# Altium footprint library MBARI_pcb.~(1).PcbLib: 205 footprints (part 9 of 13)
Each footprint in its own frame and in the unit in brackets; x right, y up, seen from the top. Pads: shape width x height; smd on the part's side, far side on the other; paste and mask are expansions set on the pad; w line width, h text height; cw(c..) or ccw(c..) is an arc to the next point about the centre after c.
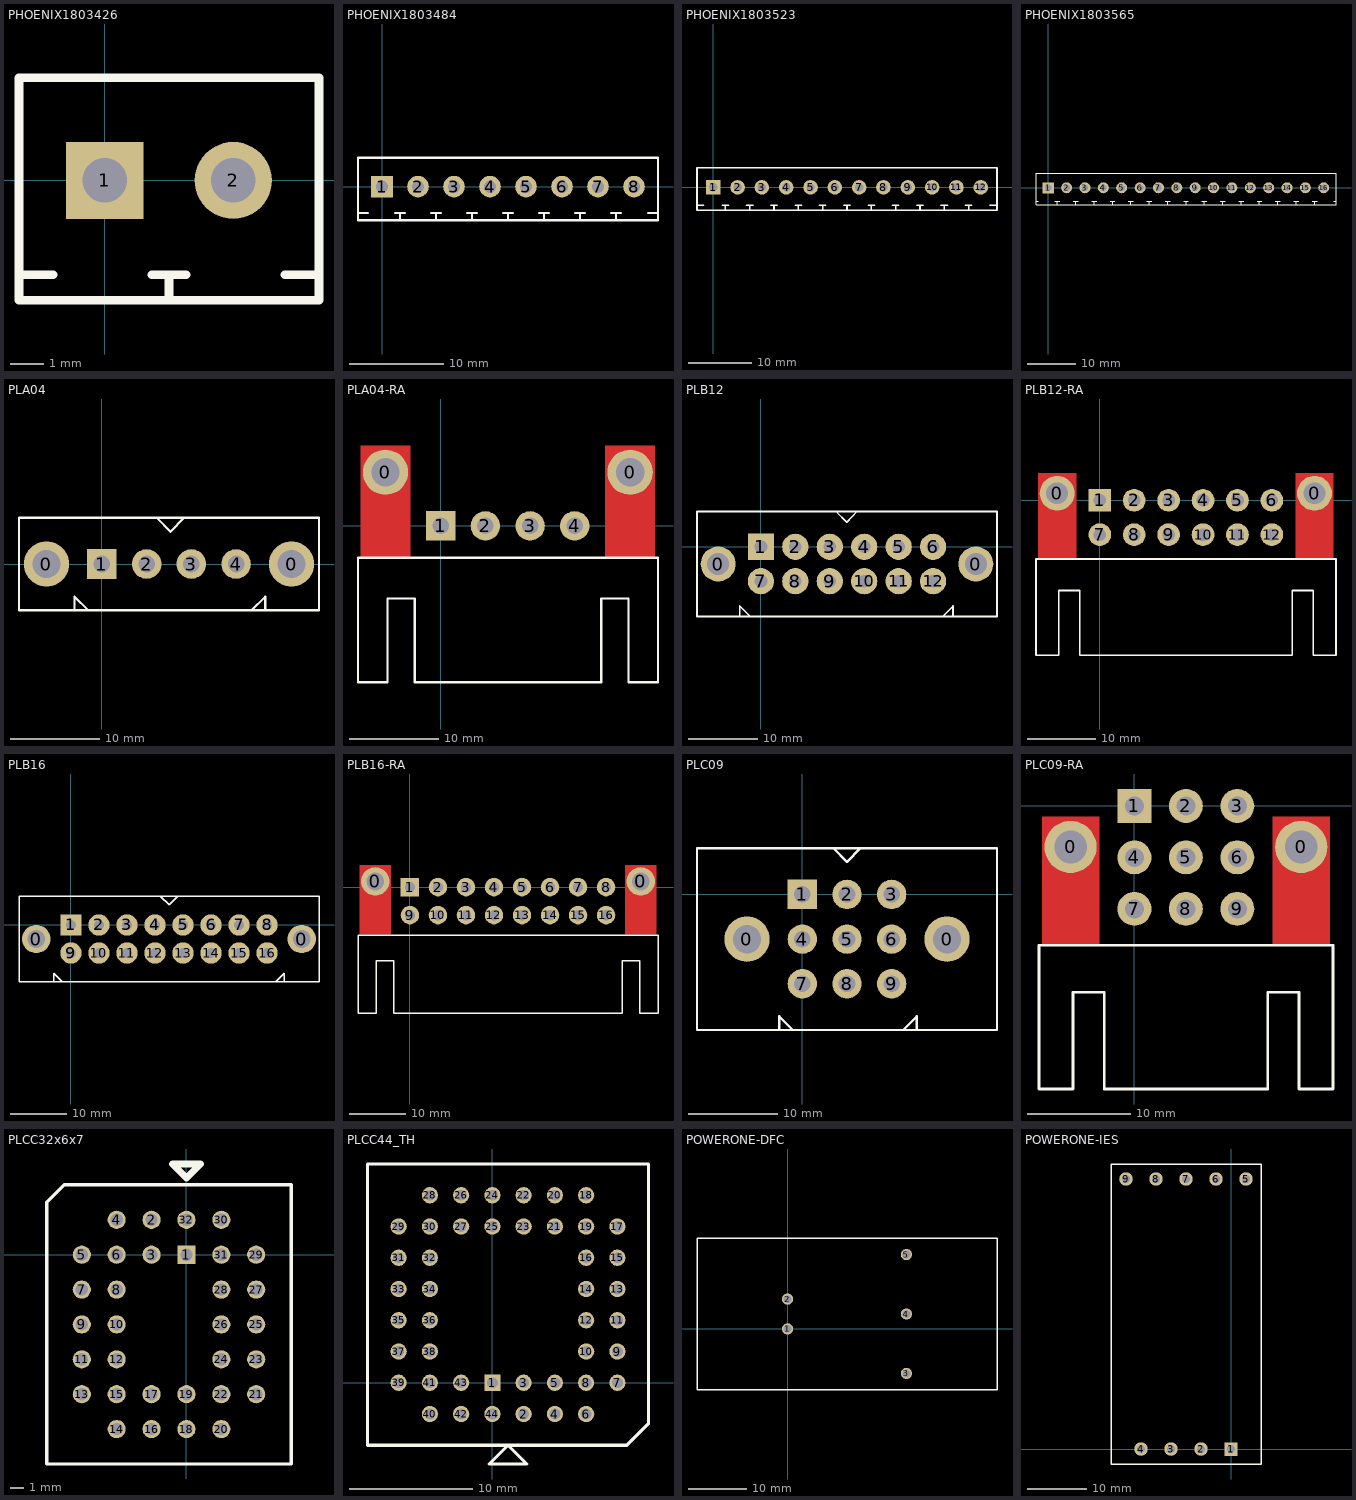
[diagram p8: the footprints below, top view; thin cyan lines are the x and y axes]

## PHOENIX1803426 [mil]
pads (2):
  rect 90x90 hole 52: 1(0,0)
  round 90 hole 52: 2(150,0)
TopOverlay:
  lines w10: -100,-110 -60,-110 ; 55,-110 95,-110 ; 75,-140 75,-110 ; 210,-110 250,-110 ; -100,-140 250,-140 250,120 -100,120 -100,-140

## PHOENIX1803484 [mil]
pads (8):
  rect 90x90 hole 52: 1(0,0)
  round 90 hole 52: 2(150,0) 3(300,0) 4(450,0) 5(600,0) 6(750,0) 7(900,0) 8(1050,0)
TopOverlay:
  lines w10: -100,-110 -60,-110 ; 55,-110 95,-110 ; 75,-140 75,-110 ; 205,-110 245,-110 ; 225,-140 225,-110 ; 355,-110 395,-110 ; 375,-140 375,-110 ; 505,-110 545,-110 ; 525,-140 525,-110 ; 655,-110 695,-110 ; 675,-140 675,-110 ; 805,-110 845,-110 ; 825,-140 825,-110 ; 955,-110 995,-110 ; 975,-140 975,-110 ; 1110,-110 1150,-110 ; -100,-140 -100,120 1150,120 1150,-140 -100,-140

## PHOENIX1803523 [mil]
pads (12):
  rect 90x90 hole 52: 1(0,0)
  round 90 hole 52: 2(150,0) 3(300,0) 4(450,0) 5(600,0) 6(750,0) 7(900,0) 8(1050,0) 9(1200,0) 10(1350,0) 11(1500,0) 12(1650,0)
TopOverlay:
  lines w10: -100,-110 -60,-110 ; 55,-110 95,-110 ; 75,-140 75,-110 ; 205,-110 245,-110 ; 225,-140 225,-110 ; 355,-110 395,-110 ; 375,-140 375,-110 ; 505,-110 545,-110 ; 525,-140 525,-110 ; 655,-110 695,-110 ; 675,-140 675,-110 ; 805,-110 845,-110 ; 825,-140 825,-110 ; 955,-110 995,-110 ; 975,-140 975,-110 ; 1105,-110 1145,-110 ; 1125,-140 1125,-110 ; 1255,-110 1295,-110 ; 1275,-140 1275,-110 ; 1405,-110 1445,-110 ; 1425,-140 1425,-110 ; 1555,-110 1595,-110 ; 1575,-140 1575,-110 ; 1705,-110 1745,-110 ; -100,-140 -100,120 1750,120 1750,-140 -100,-140

## PHOENIX1803565 [mil]
pads (16):
  rect 90x90 hole 52: 1(0,0)
  round 90 hole 52: 2(150,0) 3(300,0) 4(450,0) 5(600,0) 6(750,0) 7(900,0) 8(1050,0) 9(1200,0) 10(1350,0) 11(1500,0) 12(1650,0) 13(1800,0) 14(1950,0) 15(2100,0) 16(2250,0)
TopOverlay:
  lines w10: -100,-110 -80,-110 ; 55,-110 95,-110 ; 75,-140 75,-110 ; 205,-110 245,-110 ; 225,-140 225,-110 ; 355,-110 395,-110 ; 375,-140 375,-110 ; 505,-110 545,-110 ; 525,-140 525,-110 ; 655,-110 695,-110 ; 675,-140 675,-110 ; 805,-110 845,-110 ; 825,-140 825,-110 ; 955,-110 995,-110 ; 975,-140 975,-110 ; 1105,-110 1145,-110 ; 1125,-140 1125,-110 ; 1255,-110 1295,-110 ; 1275,-140 1275,-110 ; 1405,-110 1445,-110 ; 1425,-140 1425,-110 ; 1555,-110 1595,-110 ; 1575,-140 1575,-110 ; 1705,-110 1745,-110 ; 1725,-140 1725,-110 ; 1855,-110 1895,-110 ; 1875,-140 1875,-110 ; 2005,-110 2045,-110 ; 2025,-140 2025,-110 ; 2155,-110 2195,-110 ; 2175,-140 2175,-110 ; 2330,-110 2350,-110 ; -100,-140 2350,-140 2350,120 -100,120 -100,-140

## PLA04 [mil] "Positronic 1x4 pin"
pads (6):
  round 200 hole 125: 0(-244.5,0) 0(835.5,0)
  rect 130x130 hole 73: 1(0,0)
  round 130 hole 73: 2(197,0) 3(394,0) 4(591,0)
TopOverlay:
  lines w10: -120.5,-204 -120.5,-144 -60.5,-204 ; 242,204 302.5,142.5 362,204 ; 659.5,-204 719.5,-144 719.5,-204 ; -365.5,-204 -365.5,204 956.5,204 956.5,-204 -365.5,-204

## PLA04-RA [mil]
pads (6):
  round 200 hole 125: 0(-244.5,237) 0(835.5,237)
  rect 130x130 hole 73: 1(0,0)
  round 130 hole 73: 2(197,0) 3(394,0) 4(591,0)
TopLayer:
  rectangle: 725.5,-138 945.5,354
  rectangle: -354.5,-138 -134.5,354
TopOverlay:
  lines w10: -365.5,-690 -235.5,-690 -235.5,-320 -115.5,-320 -115.5,-690 708.5,-690 708.5,-320 828.5,-320 828.5,-690 958.5,-690 958.5,-140 -365.5,-140 -365.5,-690

## PLB12 [mil] "Positronic 2x6 pin"
pads (14):
  round 200 hole 125: 0(-244.5,-98.5) 0(1229.5,-98.5)
  rect 150x150 hole 73: 1(0,0)
  round 150 hole 73: 2(197,0) 3(394,0) 4(591,0) 5(788,0) 6(985,0) 7(0,-197) 8(197,-197) 9(394,-197) 10(591,-197) 11(788,-197) 12(985,-197)
TopOverlay:
  lines w10: -120.5,-398.5 -120.5,-338.5 -60.5,-398.5 ; 429.5,201.5 490,140 549.5,201.5 ; 1039.5,-398.5 1099.5,-338.5 1099.5,-398.5 ; -365.5,-398.5 1350.5,-398.5 1350.5,201.5 -365.5,201.5 -365.5,-398.5

## PLB12-RA [mil]
pads (14):
  round 200 hole 125: 0(-244.5,40) 0(1229.5,40)
  rect 130x130 hole 73: 1(0,0)
  round 130 hole 73: 2(197,0) 3(394,0) 4(591,0) 5(788,0) 6(985,0) 7(0,-197) 8(197,-197) 9(394,-197) 10(591,-197) 11(788,-197) 12(985,-197)
TopLayer:
  rectangle: -354.5,-335 -134.5,157
  rectangle: 1119.5,-335 1339.5,157
TopOverlay:
  lines w10: -365.5,-887 -365.5,-337 1352.5,-337 1352.5,-887 1222.5,-887 1222.5,-517 1102.5,-517 1102.5,-887 -115.5,-887 -115.5,-517 -235.5,-517 -235.5,-887 -365.5,-887

## PLB16 [mil] "Positronic 2x8 pins"
pads (18):
  round 200 hole 125: 0(-244.5,-98.5) 0(1623.5,-98.5)
  rect 150x150 hole 73: 1(0,0)
  round 150 hole 73: 2(197,0) 3(394,0) 4(591,0) 5(788,0) 6(985,0) 7(1182,0) 8(1379,0) 9(0,-197) 10(197,-197) 11(394,-197) 12(591,-197) 13(788,-197) 14(985,-197) 15(1182,-197) 16(1379,-197)
TopOverlay:
  lines w10: -120.5,-398.5 -120.5,-338.5 -60.5,-398.5 ; 629.5,201.5 689.5,141.5 749.5,201.5 ; 1439.5,-398.5 1499.5,-338.5 1499.5,-398.5 ; -365.5,-398.5 -365.5,201.5 1744.5,201.5 1744.5,-398.5 -365.5,-398.5

## PLB16-RA [mil]
pads (18):
  round 200 hole 125: 0(-244.5,40) 0(1623.5,40)
  rect 130x130 hole 73: 1(0,0)
  round 130 hole 73: 2(197,0) 3(394,0) 4(591,0) 5(788,0) 6(985,0) 7(1182,0) 8(1379,0) 9(0,-197) 10(197,-197) 11(394,-197) 12(591,-197) 13(788,-197) 14(985,-197) 15(1182,-197) 16(1379,-197)
TopLayer:
  rectangle: -354.5,-335 -134.5,157
  rectangle: 1513.5,-335 1733.5,157
TopOverlay:
  lines w10: -365.5,-887 -365.5,-337 1744.5,-337 1744.5,-887 1614.5,-887 1614.5,-517 1494.5,-517 1494.5,-887 -115.5,-887 -115.5,-517 -235.5,-517 -235.5,-887 -365.5,-887

## PLC09 [mil] "Positronic 3x3 pins"
pads (11):
  round 200 hole 125: 0(-244.5,-197) 0(638.5,-197)
  rect 130x130 hole 73: 1(0,0)
  round 130 hole 73: 2(197,0) 3(394,0) 4(0,-197) 5(197,-197) 6(394,-197) 7(0,-394) 8(197,-394) 9(394,-394)
TopOverlay:
  lines w10: -102,-598 -102,-538 -42,-598 ; 136.5,205 197,143.5 256.5,205 ; 445,-598 505,-538 505,-598 ; -465,-598 -465,204 859,204 859,-598 -465,-598

## PLC09-RA [mil]
pads (11):
  round 200 hole 125: 0(-244.5,-157) 0(638.5,-157)
  rect 130x130 hole 73: 1(0,0)
  round 130 hole 73: 2(197,0) 3(394,0) 4(0,-197) 5(197,-197) 6(394,-197) 7(0,-394) 8(197,-394) 9(394,-394)
TopLayer:
  rectangle: 528.5,-532 748.5,-40
  rectangle: -354.5,-532 -134.5,-40
TopOverlay:
  lines w10: -365.5,-1084 -235.5,-1084 -235.5,-714 -115.5,-714 -115.5,-1084 510.5,-1084 510.5,-714 630.5,-714 630.5,-1084 760.5,-1084 760.5,-534 -365.5,-534 -365.5,-1084

## PLCC32x6x7 [mil]
pads (32):
  rect 52x52 hole 35: 1(0,0)
  round 52 hole 35: 2(-100,100) 3(-100,0) 4(-200,100) 5(-300,0) 6(-200,0) 7(-300,-100) 8(-200,-100) 9(-300,-200) 10(-200,-200) 11(-300,-300) 12(-200,-300) 13(-300,-400) 14(-200,-500) 15(-200,-400) 16(-100,-500) 17(-100,-400) 18(0,-500) 19(0,-400) 20(100,-500) 21(200,-400) 22(100,-400) 23(200,-300) 24(100,-300) 25(200,-200) 26(100,-200) 27(200,-100) 28(100,-100) 29(200,0) 30(100,100) 31(100,0) 32(0,100)
TopOverlay:
  lines w10: -400,-600 300,-600 300,200 -350,200 -400,150 -400,-600
  lines w20: -40,260 0,220 40,260 -40,260

## PLCC44_TH [mil]
pads (44):
  rect 52x52 hole 35: 1(0,0)
  round 52 hole 35: 2(100,-100) 3(100,0) 4(200,-100) 5(200,0) 6(300,-100) 7(400,0) 8(300,0) 9(400,100) 10(300,100) 11(400,200) 12(300,200) 13(400,300) 14(300,300) 15(400,400) 16(300,400) 17(400,500) 18(300,600) 19(300,500) 20(200,600) 21(200,500) 22(100,600) 23(100,500) 24(0,600) 25(0,500) 26(-100,600) 27(-100,500) 28(-200,600) 29(-300,500) 30(-200,500) 31(-300,400) 32(-200,400) 33(-300,300) 34(-200,300) 35(-300,200) 36(-200,200) 37(-300,100) 38(-200,100) 39(-300,0) 40(-200,-100) 41(-200,0) 42(-100,-100) 43(-100,0) 44(0,-100)
TopOverlay:
  lines w10: -400,-200 430,-200 500,-130 500,700 -350,700 -400,700 -400,650 -400,-200 ; -10,-260 100,-260 110,-260 50,-200 -10,-260

## POWERONE-DFC [mil] "PowerOne DC->DC Converter"
height 420
pads (5):
  round 76 hole 52: 1(0,0) 2(0,200) 3(800,-300) 4(800,100) 5(800,500)
TopOverlay:
  lines w10: -610,-410 -610,610 1410,610 1410,-410 -610,-410

## POWERONE-IES [mil]
pads (9):
  rect 90x90 hole 52: 1(0,0)
  round 90 hole 52: 2(-200,0) 3(-400,0) 4(-600,0) 5(100,1800) 6(-100,1800) 7(-300,1800) 8(-500,1800) 9(-700,1800)
TopOverlay:
  lines w10: -800,-100 -800,1900 200,1900 200,-100 -800,-100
